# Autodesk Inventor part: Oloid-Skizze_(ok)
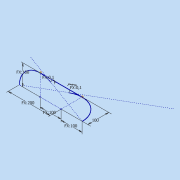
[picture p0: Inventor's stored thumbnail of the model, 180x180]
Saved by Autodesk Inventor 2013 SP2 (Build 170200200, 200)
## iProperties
Created: 2014-11
Part Number: Oloid-Skizze_(ok)
Material: Allgemein
Document SubType Name: Modeling
Designer: Besitzer
Density: 1 g/cm^3
Author: Besitzer
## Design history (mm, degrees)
sketch "Skizze1"
  geometry: L1 (-200, 0)-(0, 0); L2 (0, 0)-(0, 100); L3 (-200, 0)-(267.223, 269.752); A1 r 100 centre (0, 0) between (100, 0) and (-50, 86.603); A2 r 100 centre (0, 0) between (-50, 86.603) and (-50.087, 86.552); 1 further point
  constraints: 6 end point, 5 point on circle, 3 coincident, 2 centre point, 2 point on line, 1 horizontal, 1 perpendicular, 1 tangent
  dimensions: "Radius" = 100 distance of L1.end L2.end; "d6" = 200 distance of L1.start L1.end (= 2 x Radius); "d11" = 0.1 dimension on A2 (= Zugabe)
workpoint "Arbeitspunkt1"
sketch "Skizze2"
  geometry: L1 (100, 0)-(-100, 0); L2 (-100, 0)-(144.975, 141.436); L3 (100, 0)-(100, 100); A1 r 100 centre (100, 0) between (200, 0) and (50, 86.603); A2 r 100 centre (100, 0) between (50, 86.603) and (49.913, 86.552); 1 further point
  constraints: 6 end point, 5 point on circle, 2 centre point, 2 coincident, 2 point on line, 1 horizontal, 1 midpoint, 1 perpendicular, 1 tangent
  dimensions: "d7" = 100 distance of L1.start L3.end (= Radius); "d9" = 100 distance from line of point (0, 0) L3 (= Radius); "d10" = 100 distance of L1.end point (0, 0) (= Radius); "d12" = 0.1 dimension on A2 (= Zugabe)
workpoint "Arbeitspunkt2"
sketch "3D-Skizze1"
other parameters: "Zugabe" = 0.1 [user parameter; used in 2 equation terms]
